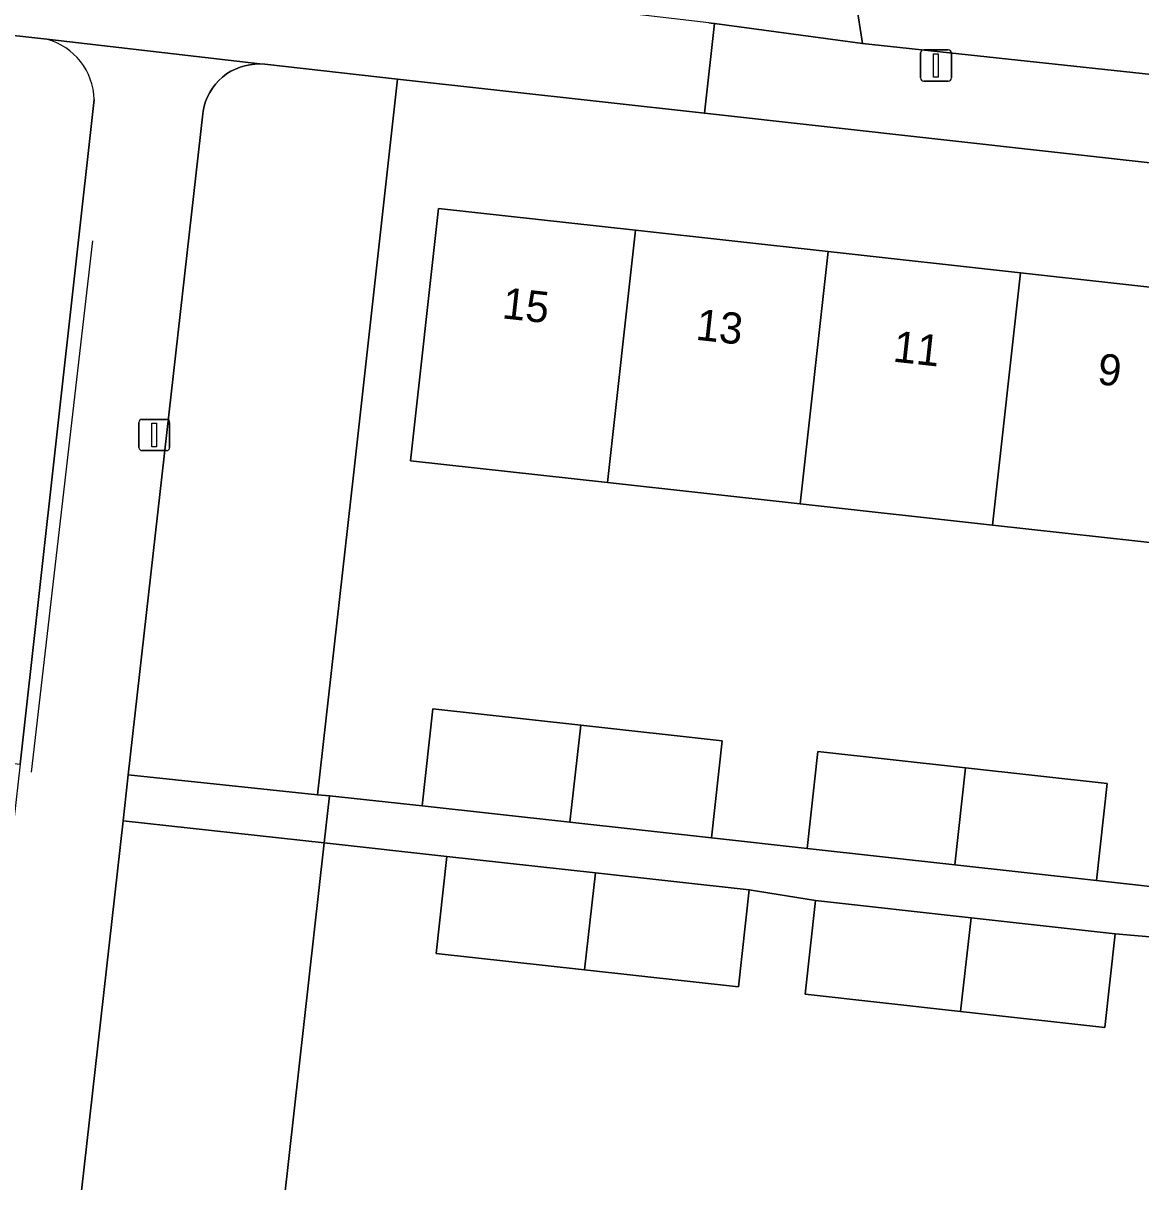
# Model space of a CAD drawing. Extents: x 162026 to 163502, y 387295 to 388169.
# Drawn here: x 162508.26 to 162544.11, y 387400.44 to 387437.62 of the extents above; entities that cross this region are included whole.
import ezdxf

# ---------------------------------------------------------------- set-up
doc = ezdxf.new("R2010")
doc.units = 0
for name, color, linetype in [('IMGEO_Erf', 7, 'Continuous'), ('IMGEO_Groenvoorziening', 7, 'Continuous'), ('IMGEO_Lichtmast', 7, 'Continuous'), ('IMGEO_Muur', 7, 'Continuous'), ('IMGEO_Pand', 7, 'Continuous'), ('IMGEO_Pand_nummerreeks', 7, 'Continuous'), ('IMGEO_Parkeervlak_open', 7, 'Continuous'), ('IMGEO_Rijbaan_lokaal_open', 7, 'Continuous'), ('IMGEO_Voetpad_open', 7, 'Continuous')]:
    doc.layers.add(name, color=color, linetype=linetype)

msp = doc.modelspace()

# ---------------------------------------------------------------- linework, layer by layer
at = {"layer": 'IMGEO_Erf'}
for points in [[(162509.017, 387437.102), (162500, 387438.095), (162465.999, 387441.839), (162463.184, 387442.149), (162461.926, 387430.151), (162461.4, 387425.126), (162461.084, 387422.106), (162468.848, 387421.233), (162473.565, 387420.703), (162473.229, 387417.716), (162500.991, 387414.639), (162501.327, 387417.676), (162506.042, 387417.154), (162505.706, 387414.116), (162508.158, 387413.846), (162510.534, 387435.171)], [(162571.372, 387430.136), (162530.112, 387434.728), (162520.267, 387435.824), (162518.852, 387423.115), (162517.702, 387412.864), (162518.083, 387412.824), (162521.056, 387412.51), (162521.4, 387415.618), (162526.14, 387415.093), (162530.678, 387414.59), (162530.334, 387411.483), (162533.406, 387411.142), (162533.75, 387414.25), (162538.489, 387413.725), (162543.028, 387413.222), (162542.684, 387410.115), (162545.757, 387409.774)], [(162569.106, 387380.869), (162571.901, 387405.298), (162567.349, 387405.805), (162566.998, 387402.656), (162562.402, 387403.168), (162557.425, 387403.722), (162557.776, 387406.872), (162555.331, 387407.118), (162554.986, 387404.025), (162550.387, 387404.537), (162545.41, 387405.091), (162545.755, 387408.185), (162543.287, 387408.404), (162542.951, 387405.396), (162538.318, 387405.912), (162533.341, 387406.466), (162533.676, 387409.475), (162531.547, 387409.808), (162531.202, 387406.697), (162526.258, 387407.245), (162521.503, 387407.772), (162521.848, 387410.882), (162517.916, 387411.315), (162514.853, 387383.996)]]:
    msp.add_lwpolyline(points, dxfattribs=at)
msp.add_lwpolyline([(162545.175, 387420.868), (162539.352, 387421.513), (162533.177, 387422.197), (162527.002, 387422.881), (162520.68, 387423.581), (162521.577, 387431.675), (162527.898, 387430.975), (162534.074, 387430.291), (162540.249, 387429.607), (162546.423, 387428.924), (162552.599, 387428.24), (162558.774, 387427.556), (162564.95, 387426.872), (162571.275, 387426.172), (162570.378, 387418.077), (162564.054, 387418.777), (162557.878, 387419.461), (162551.703, 387420.145), (162551.367, 387420.182), (162550.959, 387416.507), (162544.768, 387417.193)], close=True, dxfattribs=at)
msp.add_arc((162508.487, 387435.124), 2.047, 1.3066, 75, dxfattribs=at)
at = {"layer": 'IMGEO_Groenvoorziening'}
for points in [[(162520.267, 387435.824), (162516.008, 387436.298), (162515.847, 387436.309), (162515.686, 387436.305), (162515.526, 387436.286), (162515.368, 387436.254), (162515.213, 387436.207), (162515.064, 387436.147), (162514.92, 387436.074), (162514.783, 387435.988), (162514.655, 387435.89), (162514.536, 387435.782), (162514.427, 387435.663), (162514.329, 387435.535), (162514.243, 387435.398), (162514.17, 387435.255), (162514.109, 387435.105), (162514.062, 387434.951), (162514.03, 387434.793), (162514.018, 387434.709), (162511.63, 387413.504), (162517.702, 387412.864), (162518.852, 387423.115)], [(162514.853, 387383.996), (162517.916, 387411.315), (162511.463, 387412.025), (162508.596, 387386.572), (162508.585, 387386.405), (162508.588, 387386.238), (162508.607, 387386.072), (162508.64, 387385.908), (162508.688, 387385.748), (162508.75, 387385.593), (162508.826, 387385.444), (162508.914, 387385.302), (162509.015, 387385.169), (162509.127, 387385.046), (162509.25, 387384.932), (162509.383, 387384.831), (162509.524, 387384.741), (162509.673, 387384.665), (162509.827, 387384.602), (162509.987, 387384.553), (162510.151, 387384.519), (162510.251, 387384.505)]]:
    msp.add_lwpolyline(points, close=True, dxfattribs=at)
at = {"layer": 'IMGEO_Lichtmast'}
for p, q in [((162537.042, 387435.861), (162537.042, 387436.661)), ((162537.042, 387436.661), (162537.042, 387435.861)), ((162537.142, 387436.761), (162537.932, 387436.761)), ((162537.932, 387436.761), (162537.142, 387436.761)), ((162538.032, 387436.661), (162538.032, 387435.861)), ((162538.032, 387435.861), (162538.032, 387436.661)), ((162537.932, 387435.761), (162537.142, 387435.761)), ((162537.142, 387435.761), (162537.932, 387435.761)), ((162511.966, 387424.005), (162511.966, 387424.805)), ((162511.966, 387424.805), (162511.966, 387424.005)), ((162512.066, 387424.905), (162512.856, 387424.905)), ((162512.856, 387424.905), (162512.066, 387424.905)), ((162512.956, 387424.805), (162512.956, 387424.005)), ((162512.956, 387424.005), (162512.956, 387424.805)), ((162512.856, 387423.905), (162512.066, 387423.905)), ((162512.066, 387423.905), (162512.856, 387423.905))]:
    msp.add_line(p, q, dxfattribs=at)
for points in [[(162537.462, 387436.636), (162537.612, 387436.636), (162537.612, 387435.886), (162537.462, 387435.886), (162537.462, 387436.636)], [(162512.386, 387424.78), (162512.536, 387424.78), (162512.536, 387424.03), (162512.386, 387424.03), (162512.386, 387424.78)]]:
    msp.add_lwpolyline(points, dxfattribs=at)
for centre, start, end in [((162537.142, 387436.661), 90, 180), ((162537.142, 387436.661), 90, 180), ((162537.932, 387436.661), 0, 90), ((162537.932, 387436.661), 360, 90), ((162537.142, 387435.861), 180, 270), ((162537.142, 387435.861), 180, 270), ((162537.932, 387435.861), 270, 0), ((162537.932, 387435.861), 270, 0), ((162512.066, 387424.805), 90, 180), ((162512.066, 387424.805), 90, 180), ((162512.856, 387424.805), 0, 90), ((162512.856, 387424.805), 360, 90), ((162512.066, 387424.005), 180, 270), ((162512.066, 387424.005), 180, 270), ((162512.856, 387424.005), 270, 0), ((162512.856, 387424.005), 270, 0)]:
    msp.add_arc(centre, 0.1, start, end, dxfattribs=at)
at = {"layer": 'IMGEO_Muur'}
msp.add_lwpolyline([(162508.53, 387413.588), (162510.488, 387430.63)], dxfattribs=at)
at = {"layer": 'IMGEO_Pand'}
for points in [[(162527.898, 387430.975), (162521.577, 387431.675), (162520.68, 387423.581), (162527.002, 387422.881)], [(162527.002, 387422.881), (162533.177, 387422.197), (162534.074, 387430.291), (162527.898, 387430.975)], [(162533.177, 387422.197), (162539.352, 387421.513), (162540.249, 387429.607), (162534.074, 387430.291)], [(162546.334, 387428.117), (162546.423, 387428.924), (162540.249, 387429.607), (162539.352, 387421.513), (162545.175, 387420.868), (162545.528, 387420.829)], [(162526.14, 387415.093), (162521.4, 387415.618), (162521.056, 387412.51), (162525.796, 387411.985)], [(162525.796, 387411.985), (162530.334, 387411.483), (162530.678, 387414.59), (162526.14, 387415.093)], [(162533.75, 387414.25), (162533.406, 387411.142), (162538.145, 387410.617), (162538.489, 387413.725)], [(162542.684, 387410.115), (162543.028, 387413.222), (162538.489, 387413.725), (162538.145, 387410.617)], [(162521.848, 387410.882), (162521.503, 387407.772), (162526.258, 387407.245), (162526.613, 387410.354)], [(162531.547, 387409.808), (162526.613, 387410.354), (162526.258, 387407.245), (162531.202, 387406.697)], [(162538.661, 387408.919), (162533.676, 387409.475), (162533.341, 387406.466), (162538.318, 387405.912)], [(162538.318, 387405.912), (162542.951, 387405.396), (162543.287, 387408.404), (162538.661, 387408.919)]]:
    msp.add_lwpolyline(points, close=True, dxfattribs=at)
at = {"layer": 'IMGEO_Parkeervlak_open'}
msp.add_lwpolyline([(162530.25, 387437.63), (162530.406, 387437.607), (162530.432, 387437.605), (162535.182, 387436.966), (162531.114, 387463.071)], dxfattribs=at)
at = {"layer": 'IMGEO_Rijbaan_lokaal_open'}
msp.add_lwpolyline([(162540.563, 387448.199), (162537.24, 387469.944), (162537.082, 387470.994), (162536.24, 387476.571), (162528.88, 387477.412), (162531.114, 387463.071), (162535.182, 387436.966), (162572.06, 387433.011), (162572.882, 387440.121), (162572.776, 387440.133), (162546.338, 387443.004)], dxfattribs=at)
at = {"layer": 'IMGEO_Voetpad_open'}
for points in [[(162500, 387438.095), (162509.017, 387437.102), (162515.847, 387436.309), (162516.008, 387436.298), (162520.267, 387435.824), (162530.112, 387434.728), (162530.432, 387437.605), (162530.406, 387437.607), (162530.25, 387437.63), (162524.011, 387438.368), (162523.867, 387438.378), (162520.947, 387438.711), (162508.088, 387440.18)], [(162514.018, 387434.709), (162514.03, 387434.793), (162514.062, 387434.951), (162514.109, 387435.105), (162514.17, 387435.255), (162514.243, 387435.398), (162514.329, 387435.535), (162514.427, 387435.663), (162514.536, 387435.782), (162514.655, 387435.89), (162514.783, 387435.988), (162514.92, 387436.074), (162515.064, 387436.147), (162515.213, 387436.207), (162515.368, 387436.254), (162515.526, 387436.286), (162515.686, 387436.305), (162515.847, 387436.309), (162509.017, 387437.102)], [(162510.534, 387435.171), (162508.158, 387413.846), (162507.958, 387412.048), (162505.17, 387387.017)], [(162503.26, 387385.31), (162509.987, 387384.553), (162509.827, 387384.602), (162509.673, 387384.665), (162509.524, 387384.741), (162509.383, 387384.831), (162509.25, 387384.932), (162509.127, 387385.046), (162509.015, 387385.169), (162508.914, 387385.302), (162508.826, 387385.444), (162508.75, 387385.593), (162508.688, 387385.748), (162508.64, 387385.908), (162508.607, 387386.072), (162508.588, 387386.238), (162508.585, 387386.405), (162508.596, 387386.572), (162511.463, 387412.025), (162511.63, 387413.504), (162514.018, 387434.709)], [(162545.757, 387409.774), (162542.684, 387410.115), (162538.145, 387410.617), (162533.406, 387411.142), (162530.334, 387411.483), (162525.796, 387411.985), (162521.056, 387412.51), (162518.083, 387412.824), (162517.916, 387411.315), (162521.848, 387410.882), (162526.613, 387410.354), (162531.547, 387409.808), (162533.676, 387409.475), (162538.661, 387408.919), (162543.287, 387408.404), (162545.755, 387408.185)]]:
    msp.add_lwpolyline(points, dxfattribs=at)
for points in [[(162535.182, 387436.966), (162530.432, 387437.605), (162530.112, 387434.728), (162571.372, 387430.136), (162571.549, 387430.111), (162572.06, 387433.011)], [(162518.083, 387412.824), (162517.702, 387412.864), (162511.63, 387413.504), (162511.463, 387412.025), (162517.916, 387411.315)]]:
    msp.add_lwpolyline(points, close=True, dxfattribs=at)
msp.add_arc((162508.487, 387435.124), 2.047, 1.3066, 75, dxfattribs=at)

# ---------------------------------------------------------------- texts
at = {"layer": 'IMGEO_Pand_nummerreeks'}
for s, rotation, p in [('15', 353.6814, (162523.592, 387428.152)), ('13', 353.6814, (162529.804, 387427.464)), ('11', 353.6814, (162536.129, 387426.763)), ('9', 353.6803, (162542.686, 387426.038))]:
    msp.add_text(s, height=1, rotation=rotation, dxfattribs=at).set_placement(p)

doc.saveas('drawing.dxf')
